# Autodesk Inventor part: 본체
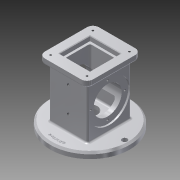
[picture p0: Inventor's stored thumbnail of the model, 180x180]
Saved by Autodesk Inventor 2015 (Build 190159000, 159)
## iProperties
Created: 2019-08
Part Number: 본체
Material: 알루미늄 6061
Document SubType Name: Modeling
Designer: now
Density: 2.7 g/cm^3
Appearance: 알루미늄 - 평지
Mass: 1031.05 g
Surface Area: 785.046 cm^2
Volume: 381.872 cm^3
Author: now
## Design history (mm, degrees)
sketch "스케치3"
  geometry: C1 r 67.5 at (0, 0); 1 further point
  constraints: 1 centre point, 1 coincident
  dimensions: "d0" = 135 diameter of C1
extrude "돌출1" new body sketch "스케치3" distance "d1" = 10; taper "d2" = 0 deg
sketch "스케치4"
  geometry: L1 (33, 37)-(-33, 37); L2 (-33, 37)-(-33, -37); L3 (-33, -37)-(33, -37); L4 (33, -37)-(33, 37); L5 (33, 37)-(-33, -37); L6 (-33, 37)-(33, -37); C1 r 67.5 at (0, 0) reference
  constraints: 12 end point, 2 midpoint, 2 parallel, 1 horizontal, 1 perpendicular
  dimensions: "d3" = 74 distance of L1.end L2.end; "d4" = 66 distance of L1.start L1.end
extrude "돌출2" join sketch "스케치4" distance "d5" = 88; taper "d6" = 0 deg
sketch "스케치5"
  geometry: L1 (67.5, 10)-(67.5, 0) reference; L2 (67.5, 0)-(-67.5, 0) reference; L3 (-67.5, 0)-(-67.5, 10) reference; L4 (-67.5, 10)-(-37, 10) reference; L5 (-37, 10)-(-37, 98) reference; L6 (-37, 98)-(37, 98) reference; L7 (37, 98)-(37, 10) reference; L8 (37, 10)-(67.5, 10) reference; L9 (-22, 98)-(-22, 24); L10 (-22, 24)-(22, 24); L11 (22, 24)-(22, 98); 1 further point
  constraints: 6 end point, 3 perpendicular, 2 point on line
  dimensions: "d7" = 74 distance between parallel lines of L10 L6; "d8" = 44 distance between parallel lines of L11 L9; "d9" = 22 distance from line of point (0, 0) L9
extrude "돌출3" cut sketch "스케치5" stored distance "d10" = 44; taper "d11" = 0 deg
sketch "스케치6"
  geometry: L1 (-22, -22)-(-22, 22) reference; L2 (-22, 22)-(22, 22) reference; L3 (22, 22)-(22, -22) reference; L4 (22, -22)-(-22, -22) reference; L5 (41, 46)-(-41, 46); L6 (-41, 46)-(-41, -46); L7 (-41, -46)-(41, -46); L8 (41, -46)-(41, 46); L9 (41, 46)-(-41, -46); L10 (-41, 46)-(41, -46); 1 further point
  constraints: 12 end point, 2 midpoint, 2 parallel, 1 horizontal, 1 perpendicular
  dimensions: "d12" = 92 distance of L5.end L6.end; "d13" = 82 distance of L6.end L7.end
extrude "돌출4" join sketch "스케치6" distance "d14" = 10; taper "d15" = 0 deg
sketch "스케치7"
  geometry: L1 (-22, 22)-(22, 22) reference; L2 (22, 22)-(22, -22) reference; L3 (22, -22)-(-22, -22) reference; L4 (-22, -22)-(-22, 22) reference; L5 (26, 26)-(-26, 26); L6 (-26, 26)-(-26, -26); L7 (-26, -26)-(26, -26); L8 (26, -26)-(26, 26); L9 (26, 26)-(-26, -26); L10 (-26, 26)-(26, -26); 1 further point
  constraints: 12 end point, 2 midpoint, 2 parallel, 1 horizontal, 1 perpendicular
  dimensions: "d16" = 52 distance of L5.end L6.end; "d17" = 52 distance of L6.end L7.end
extrude "돌출5" cut sketch "스케치7" distance "d18" = 8; taper "d19" = 0 deg
sketch "스케치8"
  geometry: L1 (0, 0)-(-88, 0) reference; L2 (10, -30.5)-(10, 104.5) reference; C1 r 35 at (-44, 37); 2 further points
  constraints: 1 centre point, 1 coincident
  dimensions: "d20" = 54 distance from line of point (-44, 37) L2; "d21" = 37 distance from line of point (-44, 37) L1; "d22" = 70 diameter of C1
extrude "돌출6" cut sketch "스케치8" distance "d23" = 3; taper "d24" = 0 deg
sketch "스케치9"
  geometry: L1 (0, 74)-(88, 74) reference; L2 (-10, 104.5)-(-10, -30.5) reference; 2 further points
  dimensions: "d25" = 54 distance from line of L2 point (44, 37); "d26" = 37 distance from line of point (44, 37) L1
hole "구멍1" sketch "스케치9" at (44, 37) diameter "d27" = 48; stored, may be unused: countersink angle "d31" = 90 deg, drill point angle "d33" = 118 deg; dims "d28" = 6, "d29" = 70, "d30" = 3, "d32" = 8
sketch "스케치10"
  geometry: C1 r 24 at (0, 0) reference; 2 further points
  constraints: 1 horizontal alignment
  dimensions: "d34" = 29 distance of C1.centre point (-29, 0)
hole "구멍2" sketch "스케치10" at (-29, 0) diameter "d35" = 3.242; stored, may be unused: countersink angle "d39" = 90 deg, drill point angle "d41" = 118 deg; dims "d36" = 4, "d37" = 70, "d38" = 3, "d40" = 6
fillet "모깎기1" dims "d45" = 10
sketch "스케치11"
  geometry: A1 r 10 centre (-31, 36) between (-31, 46) and (-41, 36) reference; A2 r 10 centre (-31, -36) between (-41, -36) and (-31, -46) reference; A3 r 10 centre (31, -36) between (31, -46) and (41, -36) reference; A4 r 10 centre (31, 36) between (41, 36) and (31, 46) reference; 1 further point
hole "구멍3" sketch "스케치11" at (-31, 36), (-31, -36), (31, -36), (31, 36) diameter "d46" = 3.242; stored, may be unused: countersink angle "d50" = 90 deg, drill point angle "d52" = 118 deg; dims "d47" = 4, "d48" = 70, "d49" = 3, "d51" = 6
sketch "스케치12"
  geometry: L1 (0, 0)-(0, 88) reference; L2 (-34.5, -10)-(100.5, -10) reference; 3 further points
  dimensions: "d53" = 37 distance from line of L2 point (33, 27); "d54" = 43 distance of point (33, 27) point (33, 70); "d55" = 33 distance from line of point (33, 70) L1; "d56" = 33 distance from line of L1 point (33, 27)
hole "구멍4" sketch "스케치12" at (33, 70), (33, 27) diameter "d57" = 4.917; stored, may be unused: countersink angle "d61" = 90 deg, drill point angle "d63" = 118 deg; dims "d58" = 12, "d59" = 70, "d60" = 3, "d62" = 40
sketch "스케치13"
  geometry: C1 r 67.5 at (0, 0) reference; A1 r 59 centre (0, 0) between (-59, 0) and (0, 59); 1 further point
  constraints: 3 point on circle, 1 centre point, 1 coincident
  dimensions: "d64" = 118 diameter of A1
hole "구멍5" sketch "스케치13" at (-59, 0), (0, 59), (59, 0) diameter "d65" = 9; stored, may be unused: countersink angle "d69" = 90 deg, drill point angle "d71" = 118 deg; dims "d66" = 12, "d67" = 70, "d68" = 3, "d70" = 40
sketch "스케치14"
  geometry: C1 r 67.5 at (0, 0) reference
hole "구멍6" sketch "스케치14" at (0, 0) diameter "d72" = 25; stored, may be unused: countersink angle "d76" = 90 deg, drill point angle "d78" = 118 deg; dims "d73" = 12, "d74" = 50, "d75" = 18, "d77" = 40
sketch "스케치15"
  geometry: C1 r 67.5 at (0, 0) reference; C2 r 59 at (0, 0)
  constraints: 1 centre point, 1 coincident, 1 other
  dimensions: "d79" = 118 diameter of C2
feature "엠보싱1" sketch "스케치15" dims "d2" = 0, "d9" = 22, "d80" = 0.5, "d81" = 0
fillet "모깎기2" dims "d82" = 3
fillet "모깎기3" dims "d83" = 3
fillet "모깎기4" dims "d84" = 3
chamfer "모따기1" distance "d85" = 3; stored, may be unused: second distance "d86" = 2, angle "d87" = 45 deg
fillet "모깎기5" dims "d88" = 3
fillet "모깎기6" dims "d89" = 3
fillet "모깎기7" dims "d90" = 3
chamfer "모따기2" distance "d91" = 1; stored, may be unused: second distance "d92" = 2, angle "d93" = 45 deg
fillet "모깎기8" dims "d94" = 3
node "솔리드1"
pattern_circular "원형 패턴1" dims angle "d43" = 360 deg
mirror "대칭1"
node "절단 모서리 투영1"
